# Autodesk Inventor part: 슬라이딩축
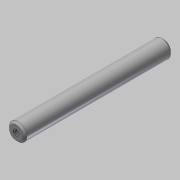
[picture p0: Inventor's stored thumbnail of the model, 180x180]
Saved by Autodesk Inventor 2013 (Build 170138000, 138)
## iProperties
Created: 2020-03
Part Number: 슬라이딩축
Material: 강철, 연강
Document SubType Name: Modeling
Designer: mduedu
Density: 1 g/cm^3
Author: mduedu
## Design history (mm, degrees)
sketch "스케치1"
  geometry: C1 r 4.5 at (0, 0); 1 further point
  constraints: 1 centre point, 1 coincident
  dimensions: "d0" = 9 diameter of C1
extrude "돌출1" new body sketch "스케치1" stored distance "d1" = 76; taper "d2" = 0 deg
hole "구멍1" diameter "d5" = 3.242; stored, may be unused: countersink angle "d9" = 90 deg, drill point angle "d11" = 118 deg; dims "d3" = 10, "d4" = 10, "d6" = 8, "d7" = 4, "d8" = 2, "d10" = 10
chamfer "모따기1" distance "d12" = 1; stored, may be unused: second distance "d13" = 2, angle "d14" = 45 deg
node "솔리드1"
mirror "대칭1"
